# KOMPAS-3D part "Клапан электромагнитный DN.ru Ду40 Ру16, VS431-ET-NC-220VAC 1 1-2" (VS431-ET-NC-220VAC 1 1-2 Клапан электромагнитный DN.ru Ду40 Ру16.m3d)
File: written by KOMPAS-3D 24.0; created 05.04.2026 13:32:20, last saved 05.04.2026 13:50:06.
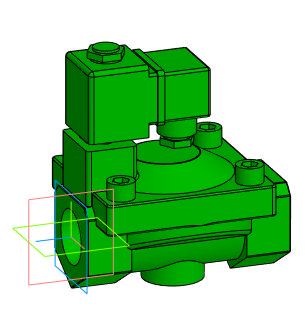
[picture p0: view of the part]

Document properties: Автор: artio; Полное имя файла: C:\Users\artio\OneDrive\Рабочий стол\Клапан электромагнитный DN.ru\VS431\VS431-ET-NC\VS431-ET-NC-220VAC\Ду40\VS431-ET-NC-220VAC 1 1-2 Клапан электромагнитный DN.ru Ду40 Ру16.m3d

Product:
- Body: Тело 1  | qty 1
    Масса: 3.859459
- Part/product: Клапан электромагнитный DN.ru Ду40 Ру16  | designation VS431-ET-NC-220VAC 1 1-2
    Масса: 2.285
    Раздел спецификации: Прочие изделия
    Примечание: D130-04709
    additional columns: ef56311e-7521-43dc-8291-0e6108b3d81d; artio; c; Шероховатость не задана; Да

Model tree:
1. Операция без истории:1

Expressions: VS431-ET-NC-220VAC 1 1-2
